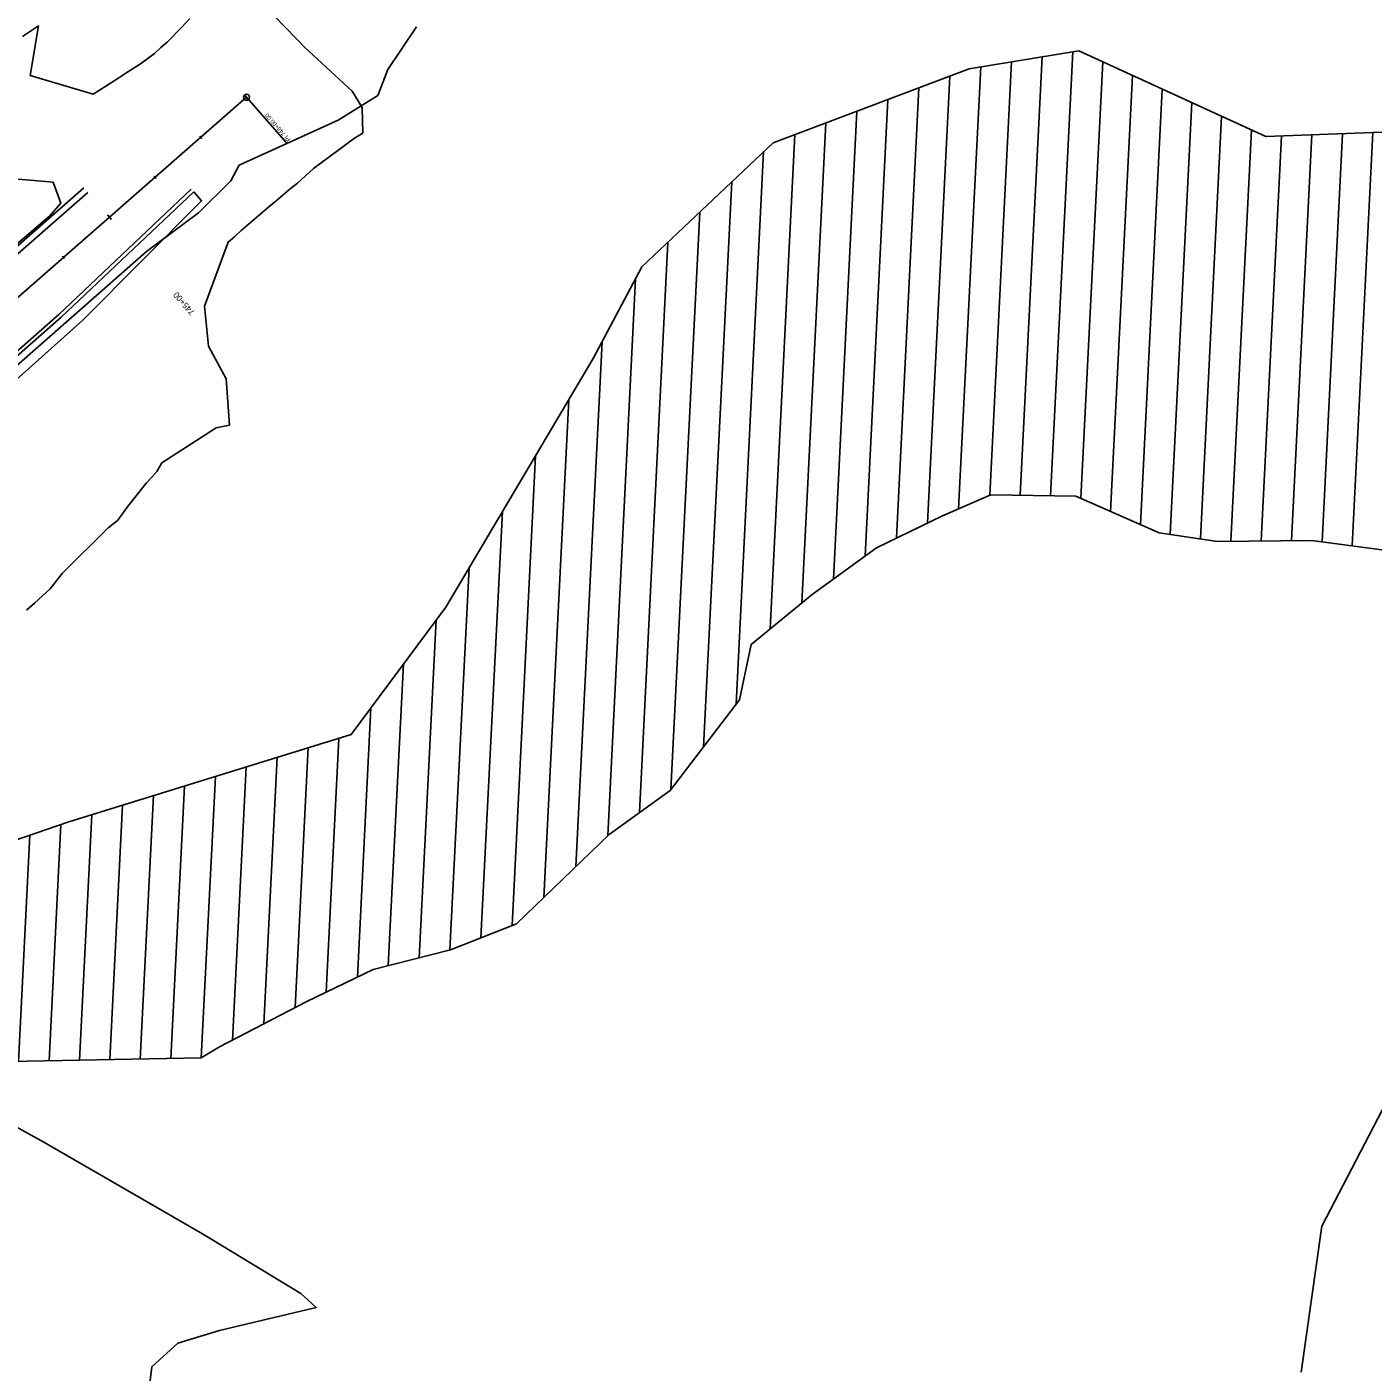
# Model space of a CAD drawing. Extents: x 1300404 to 1323571, y 234004 to 252077.
# Drawn here: x 1312432 to 1314648, y 240657 to 242870 of the extents above; entities that cross this region are included whole.
import ezdxf

# ---------------------------------------------------------------- set-up
doc = ezdxf.new("R2010")
doc.units = 0
for name, color, linetype in [('R_Const Limits', 7, 'Continuous'), ('R_Floodway', 7, 'Continuous'), ('R_Flooplain', 7, 'Continuous'), ('R_Horz Alg Annot', 7, 'Continuous'), ('R_Horz Alg Annot Leader', 7, 'Continuous'), ('R_Horz Alg Major Ticks', 7, 'Continuous'), ('R_Horz Alg Minor Ticks', 7, 'Continuous'), ('R_Horz Alg Station Annot', 7, 'Continuous'), ('R_Lane Edge', 7, 'Continuous'), ('R_Proposed', 7, 'Continuous'), ('R_Shoulder', 7, 'Continuous')]:
    doc.layers.add(name, color=color, linetype=linetype)

msp = doc.modelspace()

# ---------------------------------------------------------------- linework, layer by layer
at = {"layer": 'R_Const Limits'}
for points in [[(1312431.9, 241910.7), (1312444.9, 241922.4), (1312457.9, 241934.2), (1312470.8, 241945.9), (1312480.6, 241958.5), (1312490.3, 241971.2), (1312566.2, 242046.2), (1312581.7, 242058.2), (1312589.4, 242069.1), (1312597.2, 242080), (1312629.4, 242120.4), (1312637.8, 242129.7), (1312646.1, 242139.1), (1312654.2, 242153.4), (1312744, 242210.5), (1312765.9, 242215.2), (1312760.1, 242291.6), (1312731.3, 242345.1), (1312724.4, 242411), (1312763.7, 242516.3), (1312774.3, 242525.8), (1312784.8, 242535.3), (1312796.3, 242545.1), (1312807.7, 242554.9), (1312819.2, 242564.7), (1312830.6, 242574.4), (1312842.4, 242584.2), (1312854.1, 242594), (1312865.9, 242603.8), (1312877.6, 242613.5), (1312890.7, 242625.5), (1312903.8, 242637.5), (1312971.7, 242687.3), (1312985.5, 242695.8), (1312983.9, 242738.1), (1312967.6, 242764.9), (1312889.1, 242837.3), (1312876.5, 242850.4), (1312798.7, 242931)], [(1312700.7, 242884.5), (1312687.5, 242869.9), (1312663.6, 242845.8), (1312652.9, 242836.4), (1312642.2, 242826.9), (1312619.4, 242809.7), (1312607.4, 242802), (1312595.4, 242794.2), (1312583.4, 242786.5), (1312562.3, 242773.2), (1312541.2, 242759.9), (1312437.6, 242790.8), (1312451.6, 242872.1), (1312438.5, 242863.3), (1312425.3, 242854.5)], [(1312707, 242599.1), (1312719.9, 242584.1), (1312524.9, 242388.2), (1311988.1, 241908.5)]]:
    msp.add_lwpolyline(points, dxfattribs=at)
at = {"layer": 'R_Floodway'}
for p, q in [((1314117.3, 242099), (1314153.9, 242829.6)), ((1314017.2, 242099.9), (1314052.9, 242813)), ((1314067.3, 242099.8), (1314103.4, 242821.3)), ((1314167.1, 242094.8), (1314203.1, 242813.3)), ((1313914.8, 242053.9), (1313951.6, 242789.6)), ((1313966, 242077.5), (1314002.5, 242804.7)), ((1314216.1, 242073.3), (1314252.1, 242790.8)), ((1313863.5, 242029.2), (1313900.6, 242770.4)), ((1314265.1, 242051.9), (1314301, 242768.3)), ((1313811.9, 241999.8), (1313849.6, 242751.2)), ((1314314.4, 242035.5), (1314349.9, 242745.8)), ((1313760, 241961.8), (1313798.6, 242732)), ((1314364, 242028), (1314398.9, 242723.3)), ((1313707.9, 241922.4), (1313747.5, 242712.8)), ((1314413.9, 242024), (1314447.8, 242700.8)), ((1314613.8, 242016.5), (1314647.9, 242696.6)), ((1313655.8, 241880), (1313696.5, 242693.6)), ((1314464, 242024.6), (1314497.4, 242690.9)), ((1314514.1, 242025.2), (1314547.5, 242692.8)), ((1314564.1, 242023.3), (1314597.7, 242694.7)), ((1313599.5, 241755.9), (1313645, 242665.4)), ((1313545.9, 241685.8), (1313592.5, 242615.6)), ((1313492.3, 241615.6), (1313539.9, 242565.8)), ((1313440.4, 241577.5), (1313487.4, 242516)), ((1313388.4, 241539.5), (1313434.3, 242456.1)), ((1313335.8, 241488.7), (1313379, 242352)), ((1313283.2, 241437.9), (1313324.2, 242256.8)), ((1313230.8, 241391.7), (1313269.5, 242164.9)), ((1313179.7, 241371.5), (1313214.9, 242072.9)), ((1313128.7, 241351.5), (1313160.2, 241980.9)), ((1313077.9, 241338.6), (1313105.8, 241894.7)), ((1313027.2, 241325.8), (1313052.1, 241822.2)), ((1312976.2, 241306.9), (1312998.4, 241749.8)), ((1312924.9, 241282.2), (1312945.9, 241699.8)), ((1312873.6, 241256.6), (1312895, 241684.1)), ((1312822.2, 241229.9), (1312844.2, 241668.4)), ((1312719.3, 241174), (1312742.5, 241636.9)), ((1312770.8, 241203.1), (1312793.3, 241652.6)), ((1312669.1, 241173), (1312691.6, 241621.2)), ((1312568.9, 241171), (1312589.9, 241589.8)), ((1312619, 241172), (1312640.8, 241605.5)), ((1312518.8, 241170), (1312539, 241574.1)), ((1312468.7, 241169), (1312488.2, 241557.9)), ((1312418.6, 241168), (1312437.2, 241540.4))]:
    msp.add_line(p, q, dxfattribs=at)
for points in [[(1312353.8, 241511.8), (1312501.5, 241562.5), (1312965.9, 241706), (1313121.6, 241915.9), (1313364.5, 242324.7), (1313444.6, 242475.5), (1313660.5, 242680), (1313983.5, 242801.6), (1314164, 242831.2), (1314471.5, 242689.9), (1314663, 242697.2)], [(1314715.5, 242002.6), (1314547.3, 242025.6), (1314392.3, 242023.7), (1314296.3, 242038.2), (1314159, 242098.4), (1314018.7, 242100.6), (1313939.6, 242065.9), (1313830.5, 242013.3), (1313725, 241936.3), (1313624.2, 241854.3), (1313605.1, 241763.3), (1313491.2, 241614.2), (1313390.9, 241541.8), (1313238.4, 241394.7), (1313129.8, 241351.8), (1313002.3, 241319.5), (1312893.3, 241266.9), (1312749.2, 241191.9), (1312719.3, 241174), (1312375.3, 241167.2)]]:
    msp.add_lwpolyline(points, dxfattribs=at)
at = {"layer": 'R_Flooplain'}
for p, q in [((1313073.5, 242870.5), (1313026.5, 242800.2)), ((1313026.5, 242800.2), (1313009.9, 242757.5)), ((1313009.9, 242757.5), (1312944.9, 242717.2)), ((1312944.9, 242717.2), (1312781.6, 242643.2)), ((1312781.6, 242643.2), (1312768.2, 242617.3)), ((1312475.3, 242615.1), (1312405.4, 242621)), ((1312488.1, 242580.6), (1312475.3, 242615.1)), ((1312768.2, 242617.3), (1312714.7, 242564.3)), ((1312470.1, 242559.7), (1312488.1, 242580.6)), ((1312714.7, 242564.3), (1312629.3, 242500.9)), ((1311459.5, 241700.8), (1312470.1, 242559.7)), ((1312629.3, 242500.9), (1311599.5, 241597)), ((1314563.7, 240897.2), (1314763, 241280.4)), ((1314529.9, 240657), (1314563.7, 240897.2))]:
    msp.add_line(p, q, dxfattribs=at)
msp.add_lwpolyline([(1312137.5, 241213.6), (1312460.1, 241035.3), (1312721.2, 240884.2), (1312883.2, 240786.5), (1312908.7, 240763.4), (1312749.5, 240725.5), (1312680.8, 240704.7), (1312637.7, 240665.8), (1312633.5, 240629.7)], dxfattribs=at)
at = {"layer": 'R_Horz Alg Annot Leader'}
msp.add_lwpolyline([(1312793.8, 242754.8), (1312859.6, 242679.5)], dxfattribs=at)
at = {"layer": 'R_Horz Alg Major Ticks'}
for points in [[(1312790.5, 242758.5), (1312797.1, 242751)], [(1312564.7, 242561.1), (1312571.3, 242553.5)]]:
    msp.add_lwpolyline(points, dxfattribs=at)
at = {"layer": 'R_Horz Alg Minor Ticks'}
for points in [[(1312792.2, 242756.7), (1312795.4, 242752.9)], [(1312716.9, 242690.8), (1312720.2, 242687.1)], [(1312641.6, 242625), (1312644.9, 242621.2)], [(1312491, 242493.4), (1312494.3, 242489.6)]]:
    msp.add_lwpolyline(points, dxfattribs=at)
at = {"layer": 'R_Lane Edge'}
for p, q in [((1312325.2, 242416.8), (1312532.4, 242598)), ((1312484.9, 242397), (1312702.8, 242603.5)), ((1312070.6, 242034.7), (1312484.9, 242397))]:
    msp.add_line(p, q, dxfattribs=at)
at = {"layer": 'R_Proposed'}
msp.add_line((1308463.1, 238968), (1312793.8, 242754.8), dxfattribs=at)
msp.add_circle((1312793.8, 242754.8), 5, dxfattribs=at)
at = {"layer": 'R_Shoulder'}
for p, q in [((1312226, 242343.3), (1312525.8, 242605.5)), ((1312488.9, 242392.6), (1312707, 242599.1)), ((1312074.6, 242030.2), (1312488.9, 242392.6))]:
    msp.add_line(p, q, dxfattribs=at)

# ---------------------------------------------------------------- texts
at = {"layer": 'R_Horz Alg Annot'}
msp.add_text('PI 748+00.00', height=7, rotation=131.1667, dxfattribs=at).set_placement((1312866.7, 242685.7))
at = {"layer": 'R_Horz Alg Station Annot'}
msp.add_text('745+00', height=10, rotation=131.1667, dxfattribs=at).set_placement((1312709.5, 242401.6))

doc.saveas('drawing.dxf')
